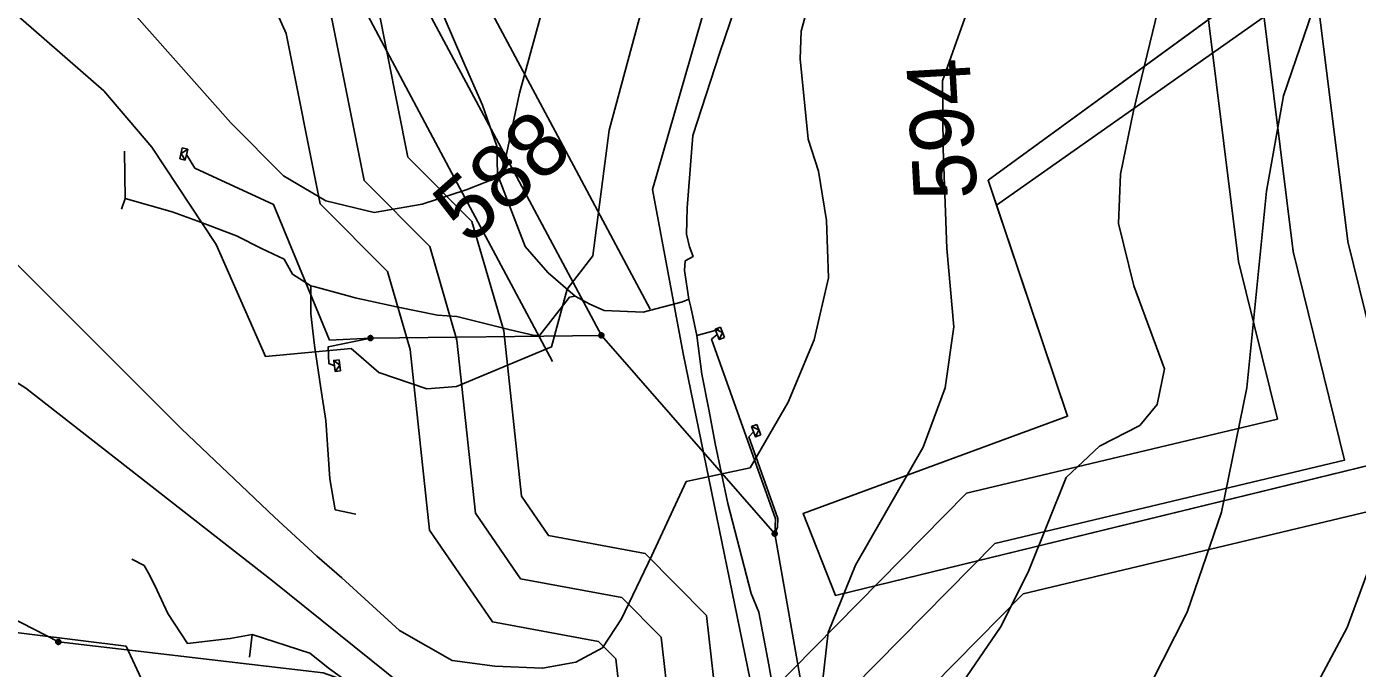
# Model space of a CAD drawing. Extents: x -709418 to -703832, y -1161719 to -1157826.
# Drawn here: x -707200.1 to -707032.1, y -1159896.5 to -1159815.5 of the extents above; entities that cross this region are included whole.
import ezdxf

# ---------------------------------------------------------------- set-up
doc = ezdxf.new("R2010")
doc.units = 0
for name, color, linetype in [('102_obvod PÚ', 7, 'Continuous'), ('110_silnice II. třídy a III. třídy', 7, 'Continuous'), ('120_vrstevnice hlavní', 7, 'Continuous'), ('121_vrstevnice hlavní_popis', 7, 'Continuous'), ('122_vrstevnice základní', 7, 'Continuous'), ('206_TTP_KN', 7, 'Continuous'), ('210_ostatní plocha_KN', 7, 'Continuous'), ('501_vodní tok', 7, 'Continuous'), ('708_el NN nadzemní a podzemní_ E.ON', 7, 'Continuous'), ('717_elektronická komunikace O2', 7, 'Continuous'), ('735_OP sítí TI', 7, 'Continuous')]:
    doc.layers.add(name, color=color, linetype=linetype)

# ---------------------------------------------------------------- blocks, each defined once
blk = doc.blocks.new('Elektro - Implicitní$0$NN4601')
for points in [[(0.63, 0), (0.62, 0.07), (0.61, 0.13), (0.6, 0.2), (0.57, 0.26), (0.54, 0.32), (0.51, 0.37), (0.47, 0.42), (0.42, 0.47), (0.37, 0.51), (0.31, 0.55), (0.25, 0.58), (0.19, 0.6), (0.13, 0.62), (0.06, 0.63), (0, 0.63), (-0.07, 0.63), (-0.13, 0.62), (-0.2, 0.6), (-0.26, 0.58), (-0.32, 0.55), (-0.37, 0.51), (-0.42, 0.47), (-0.47, 0.42), (-0.51, 0.37), (-0.55, 0.32), (-0.58, 0.26), (-0.6, 0.2), (-0.62, 0.13), (-0.63, 0.07), (-0.63, 0), (-0.63, -0.07), (-0.62, -0.13), (-0.6, -0.19), (-0.58, -0.26), (-0.55, -0.31), (-0.51, -0.37), (-0.47, -0.42), (-0.42, -0.47), (-0.37, -0.51), (-0.32, -0.54), (-0.26, -0.57), (-0.2, -0.6), (-0.13, -0.62), (-0.07, -0.63), (0, -0.63), (0.06, -0.63), (0.13, -0.62), (0.19, -0.6), (0.25, -0.57), (0.31, -0.54), (0.37, -0.51), (0.42, -0.47), (0.47, -0.42), (0.51, -0.37), (0.54, -0.31), (0.57, -0.26), (0.6, -0.19), (0.61, -0.13), (0.62, -0.07), (0.63, 0)], [(0.47, 0), (0.47, 0.05), (0.46, 0.1), (0.45, 0.15), (0.43, 0.19), (0.41, 0.24), (0.38, 0.28), (0.35, 0.32), (0.31, 0.35), (0.28, 0.38), (0.23, 0.41), (0.19, 0.43), (0.14, 0.45), (0.1, 0.46), (0.05, 0.47), (0, 0.47), (-0.05, 0.47), (-0.1, 0.46), (-0.15, 0.45), (-0.19, 0.43), (-0.24, 0.41), (-0.28, 0.38), (-0.32, 0.35), (-0.35, 0.32), (-0.38, 0.28), (-0.41, 0.24), (-0.43, 0.19), (-0.45, 0.15), (-0.46, 0.1), (-0.47, 0.05), (-0.47, 0), (-0.47, -0.05), (-0.46, -0.1), (-0.45, -0.15), (-0.43, -0.19), (-0.41, -0.24), (-0.38, -0.28), (-0.35, -0.32), (-0.32, -0.35), (-0.28, -0.38), (-0.24, -0.41), (-0.19, -0.43), (-0.15, -0.45), (-0.1, -0.46), (-0.05, -0.47), (0, -0.47), (0.05, -0.47), (0.1, -0.46), (0.14, -0.45), (0.19, -0.43), (0.23, -0.41), (0.28, -0.38), (0.31, -0.35), (0.35, -0.32), (0.38, -0.28), (0.41, -0.24), (0.43, -0.19), (0.45, -0.15), (0.46, -0.1), (0.47, -0.05), (0.47, 0)], [(0.31, 0), (0.31, 0.03), (0.31, 0.07), (0.3, 0.1), (0.29, 0.13), (0.27, 0.16), (0.25, 0.19), (0.23, 0.21), (0.21, 0.23), (0.18, 0.26), (0.15, 0.27), (0.13, 0.29), (0.09, 0.3), (0.06, 0.31), (0.03, 0.31), (0, 0.32), (-0.04, 0.31), (-0.07, 0.31), (-0.1, 0.3), (-0.13, 0.29), (-0.16, 0.27), (-0.19, 0.26), (-0.21, 0.23), (-0.24, 0.21), (-0.26, 0.19), (-0.28, 0.16), (-0.29, 0.13), (-0.3, 0.1), (-0.31, 0.07), (-0.32, 0.03), (-0.32, 0), (-0.32, -0.03), (-0.31, -0.06), (-0.3, -0.1), (-0.29, -0.13), (-0.28, -0.16), (-0.26, -0.18), (-0.24, -0.21), (-0.21, -0.23), (-0.19, -0.25), (-0.16, -0.27), (-0.13, -0.29), (-0.1, -0.3), (-0.07, -0.31), (-0.04, -0.31), (0, -0.31), (0.03, -0.31), (0.06, -0.31), (0.09, -0.3), (0.13, -0.29), (0.15, -0.27), (0.18, -0.25), (0.21, -0.23), (0.23, -0.21), (0.25, -0.18), (0.27, -0.16), (0.29, -0.13), (0.3, -0.1), (0.31, -0.06), (0.31, -0.03), (0.31, 0)], [(0.15, 0), (0.15, 0.02), (0.15, 0.03), (0.15, 0.05), (0.14, 0.06), (0.13, 0.08), (0.13, 0.09), (0.11, 0.11), (0.1, 0.12), (0.09, 0.13), (0.08, 0.14), (0.06, 0.14), (0.05, 0.15), (0.03, 0.15), (0.01, 0.16), (0, 0.16), (-0.02, 0.16), (-0.04, 0.15), (-0.05, 0.15), (-0.07, 0.14), (-0.08, 0.14), (-0.09, 0.13), (-0.11, 0.12), (-0.12, 0.11), (-0.13, 0.09), (-0.14, 0.08), (-0.15, 0.06), (-0.15, 0.05), (-0.16, 0.03), (-0.16, 0.02), (-0.16, 0), (-0.16, -0.02), (-0.16, -0.03), (-0.15, -0.05), (-0.15, -0.06), (-0.14, -0.08), (-0.13, -0.09), (-0.12, -0.1), (-0.11, -0.12), (-0.09, -0.13), (-0.08, -0.14), (-0.07, -0.14), (-0.05, -0.15), (-0.04, -0.15), (-0.02, -0.16), (0, -0.16), (0.01, -0.16), (0.03, -0.15), (0.05, -0.15), (0.06, -0.14), (0.08, -0.14), (0.09, -0.13), (0.1, -0.12), (0.11, -0.1), (0.13, -0.09), (0.13, -0.08), (0.14, -0.06), (0.15, -0.05), (0.15, -0.03), (0.15, -0.02), (0.15, 0)]]:
    blk.add_lwpolyline(points)
blk = doc.blocks.new('Elektro - Implicitní$0$NN6301')
for points in [[(0, -0.7), (-0.7, 0)], [(-0.7, -0.7), (-0.7, 0), (0.7, 0), (0.7, -0.7)], [(-0.7, -0.7), (0.7, -0.7)], [(0, -0.7), (0.7, 0)]]:
    blk.add_lwpolyline(points)

msp = doc.modelspace()

# ---------------------------------------------------------------- linework, layer by layer
at = {"layer": '102_obvod PÚ'}
msp.add_lwpolyline([(-707010.73, -1159866.04), (-707098, -1159887.31), (-707102.07, -1159876.96), (-707068.67, -1159864.69), (-707078.71, -1159834.91), (-707035.83, -1159803.63), (-707037.98, -1159798.97), (-707026.49, -1159799.82)], dxfattribs=at)
at = {"layer": '110_silnice II. třídy a III. třídy'}
for points in [[(-707796.68, -1159073.19), (-707758.86, -1159190.4), (-707734.44, -1159300.73), (-707726.3, -1159328.96), (-707710.98, -1159361.01), (-707689.44, -1159398.33), (-707672.68, -1159420.33), (-707591.22, -1159519.21), (-707503.14, -1159616.33), (-707475.85, -1159642.64), (-707378.49, -1159735.32), (-707320.09, -1159789.38), (-707255.46, -1159826.22), (-707200.25, -1159861.16), (-707169.1, -1159885.49), (-707119.45, -1159925.38), (-707100.71, -1159937.16)], [(-707024.62, -1159709.14), (-707041.49, -1159737.56), (-707056.44, -1159754.43), (-707079.58, -1159768.89), (-707097.91, -1159784.3), (-707112.85, -1159807.43), (-707121.1, -1159836.07), (-707117.24, -1159856.79), (-707092.17, -1159978.7), (-707074.33, -1160037.97), (-707032.37, -1160169.9), (-707002, -1160241.7)]]:
    msp.add_lwpolyline(points, dxfattribs=at)
at = {"layer": '120_vrstevnice hlavní'}
for points in [[(-707205.15, -1159810.75), (-707190.4, -1159823.62), (-707184.32, -1159830.71), (-707176.22, -1159843.01), (-707169.95, -1159857.17), (-707159.17, -1159856.16), (-707155.66, -1159859.17), (-707149.61, -1159861.23), (-707145.85, -1159860.94), (-707133.84, -1159855.91), (-707131.86, -1159848.66), (-707128.63, -1159844.45), (-707126.57, -1159828.58), (-707121.35, -1159809.21), (-707109.76, -1159787.95)], [(-707019.17, -1159817.65), (-707021.25, -1159822.81), (-707022.72, -1159832.33), (-707024.44, -1159848.71), (-707025.98, -1159863.09), (-707027.8, -1159873.77), (-707029.57, -1159881.11), (-707033.38, -1159891.38)], [(-707216.34, -1159978.04), (-707182.88, -1159987.8), (-707157.42, -1159997.78), (-707138.33, -1160002.69), (-707131.96, -1160002.69), (-707124.44, -1160000.96), (-707117.93, -1159997.78), (-707108.38, -1159989.68), (-707095.54, -1159978.02), (-707089.51, -1159976.77), (-707087.7, -1159971.45), (-707081.19, -1159954.24), (-707068.69, -1159936.85), (-707069.19, -1159933.09), (-707049.95, -1159922.42), (-707033.38, -1159891.38)]]:
    msp.add_lwpolyline(points, dxfattribs=at)
at = {"layer": '122_vrstevnice základní'}
for points in [[(-707052.12, -1159667.7), (-707058.77, -1159683.32), (-707066.58, -1159697.93), (-707075.26, -1159712.25), (-707080.03, -1159722.37), (-707087.55, -1159735.82), (-707094.06, -1159743.64), (-707114.75, -1159772.42), (-707126.03, -1159785.29), (-707131.82, -1159794.69), (-707132.83, -1159797.44), (-707134.56, -1159811.76), (-707137.89, -1159823.91), (-707140.11, -1159834.34), (-707144.62, -1159836.1), (-707150.19, -1159837.94), (-707156.26, -1159838.96), (-707162.34, -1159837.51), (-707167.69, -1159834.33), (-707174.34, -1159827.67), (-707208.48, -1159789.2), (-707227.33, -1159771.32)], [(-707023.48, -1159753.62), (-707035.92, -1159764.32), (-707039.77, -1159767.75), (-707043.66, -1159770.55), (-707049.03, -1159770.81), (-707053.64, -1159776.95), (-707067.94, -1159793.19), (-707074.26, -1159801.48), (-707078.37, -1159808.14), (-707081.64, -1159814.46), (-707084.45, -1159822.37), (-707084.4, -1159830.93), (-707083.9, -1159843.51), (-707083.03, -1159853.41), (-707084.14, -1159861.11), (-707086.92, -1159868.61), (-707095.44, -1159883.48), (-707098.9, -1159891.99), (-707099.86, -1159900.52)], [(-707084.08, -1159901.44), (-707077.14, -1159891.32), (-707073.67, -1159884.37), (-707068.86, -1159872.43), (-707064.62, -1159868.47), (-707059.55, -1159865.85), (-707057.34, -1159863.2), (-707056.44, -1159858.69), (-707060.32, -1159848.25), (-707062.23, -1159840.35), (-707061.97, -1159834.15), (-707060.36, -1159826.13), (-707057.27, -1159813.49), (-707052.94, -1159803.32), (-707046.47, -1159795.54), (-707041.24, -1159792.76), (-707035.99, -1159788.64), (-707027.01, -1159781.03)], [(-707058.19, -1159898.55), (-707053.56, -1159889.44), (-707049.25, -1159876.81), (-707046.03, -1159861.11), (-707043.56, -1159836.26), (-707041.39, -1159824.24), (-707037.73, -1159813.57), (-707031.9, -1159803.6)], [(-707202.26, -1159844.6), (-707180.56, -1159866.29), (-707168.85, -1159877.43), (-707163.48, -1159882.36), (-707160.33, -1159885.09), (-707153.04, -1159891.73), (-707146.38, -1159895.51), (-707141.02, -1159896.26), (-707134.98, -1159896.5), (-707130.78, -1159895.72), (-707127.4, -1159893.92), (-707125, -1159890.26), (-707121.16, -1159882.29), (-707116.84, -1159872.95), (-707108.76, -1159871.22), (-707103.96, -1159862.9), (-707100.66, -1159855.06), (-707098.88, -1159847.2), (-707099.12, -1159839.98), (-707100.14, -1159833.75), (-707101.44, -1159829.7), (-707102.45, -1159819.57), (-707102.31, -1159816.1), (-707100.72, -1159810.17)], [(-707185.12, -1159898.99), (-707187.57, -1159893.71), (-707217.45, -1159890.02), (-707237.26, -1159884.23), (-707261.56, -1159880.04), (-707287.02, -1159874.39), (-707308.43, -1159871.79), (-707324.05, -1159872.66), (-707332.73, -1159874.68), (-707341.41, -1159877.86), (-707351.82, -1159883.51), (-707360.5, -1159886.83), (-707370.91, -1159888.57), (-707388.27, -1159889.87), (-707409.1, -1159893.49), (-707421.25, -1159896.81)]]:
    msp.add_lwpolyline(points, dxfattribs=at)
at = {"layer": '206_TTP_KN'}
for p, q in [((-707077.65, -1159838.04), (-707039.33, -1159811.08)), ((-707068.67, -1159864.69), (-707077.65, -1159838.04)), ((-707102.07, -1159876.96), (-707068.67, -1159864.69)), ((-707017.62, -1159867.72), (-707098, -1159887.31)), ((-707098, -1159887.31), (-707102.07, -1159876.96))]:
    msp.add_line(p, q, dxfattribs=at)
at = {"layer": '210_ostatní plocha_KN'}
for p, q in [((-707078.71, -1159834.91), (-707040.8, -1159807.26)), ((-707039.33, -1159811.08), (-707077.65, -1159838.04)), ((-707077.65, -1159838.04), (-707078.71, -1159834.91))]:
    msp.add_line(p, q, dxfattribs=at)
at = {"layer": '501_vodní tok'}
msp.add_lwpolyline([(-707117.83, -1159911.76), (-707120.01, -1159892.59), (-707124.98, -1159887.57), (-707137.77, -1159885.21), (-707143.44, -1159876.93), (-707145.8, -1159855.09), (-707149.23, -1159843.26), (-707157.52, -1159834.93), (-707161.59, -1159814.53), (-707168, -1159800.19), (-707176.15, -1159790.23), (-707184.16, -1159776.65), (-707186.56, -1159766.68), (-707192.31, -1159754.77), (-707207.48, -1159720.69), (-707222.65, -1159685.23), (-707238.46, -1159647.82)], dxfattribs=at)
at = {"layer": '708_el NN nadzemní a podzemní_ E.ON'}
for points in [[(-707127.55, -1159854.48), (-707139.23, -1159832.61), (-707150.92, -1159810.75), (-707160.51, -1159780.45)], [(-707096.69, -1159911.5), (-707097.56, -1159911.58), (-707098.74, -1159901.93), (-707077.85, -1159880.75), (-707033.69, -1159870.23), (-707040.19, -1159843.89), (-707046.72, -1159791.33), (-707049.68, -1159783.1), (-707056.82, -1159786.08)], [(-707156.71, -1159854.83), (-707161.87, -1159855.08), (-707168.95, -1159837.96), (-707178.89, -1159833.37), (-707179.96, -1159831.67)], [(-707127.55, -1159854.48), (-707156.71, -1159854.83)], [(-707098.68, -1159918.98), (-707105.66, -1159879.52), (-707127.55, -1159854.48)], [(-707105.66, -1159879.52), (-707105.55, -1159877.63), (-707113.63, -1159854.97), (-707112.92, -1159854.36)], [(-707156.71, -1159854.83), (-707162.07, -1159855.94), (-707161.97, -1159858.04), (-707161.27, -1159858.34)], [(-707099.6, -1159919.34), (-707130.61, -1159908.39), (-707162.68, -1159897.07), (-707196.13, -1159893.18), (-707220.82, -1159880.51), (-707245.5, -1159867.84), (-707266.54, -1159866.85), (-707268.56, -1159866.76)], [(-707105.66, -1159879.52), (-707105.31, -1159878.69), (-707105.25, -1159877.59), (-707108.91, -1159867.31), (-707108.33, -1159866.65)]]:
    msp.add_lwpolyline(points, dxfattribs=at)
at = {"layer": '717_elektronická komunikace O2'}
for points in [[(-707155.55, -1159770.95), (-707157, -1159772.76), (-707159.59, -1159775.27), (-707161.97, -1159777.74), (-707163.41, -1159780.99), (-707163.34, -1159783.81), (-707161.81, -1159789.78), (-707159.5, -1159794.87), (-707156.64, -1159798.53), (-707153.56, -1159803.61), (-707152.12, -1159806.76), (-707149.31, -1159811.05), (-707147.4, -1159814.3), (-707145.06, -1159819.8), (-707142.58, -1159825.42), (-707140.75, -1159830.6), (-707140.67, -1159834.16), (-707137.16, -1159843.27), (-707135.49, -1159845.21), (-707134.26, -1159846.59), (-707130.87, -1159849.52)], [(-707116.52, -1159849.9), (-707117.07, -1159846.3), (-707116.97, -1159845.09), (-707115.97, -1159844.54), (-707116.42, -1159843.3), (-707116.82, -1159841.72), (-707116.71, -1159838.38), (-707115.99, -1159829.26), (-707112.62, -1159818.9), (-707108.56, -1159806.88), (-707107.9, -1159805.48), (-707106.35, -1159802.73), (-707101.79, -1159795.1), (-707099.85, -1159792.26), (-707097.89, -1159789.85), (-707096.06, -1159787.35), (-707091.72, -1159782.83), (-707088, -1159779.96)], [(-707097.89, -1159789.85), (-707099.85, -1159792.26), (-707101.79, -1159795.1), (-707106.35, -1159802.73), (-707107.9, -1159805.48), (-707108.56, -1159806.88), (-707112.62, -1159818.9), (-707115.99, -1159829.26), (-707116.71, -1159838.38), (-707116.82, -1159841.72), (-707116.42, -1159843.3), (-707115.97, -1159844.54)], [(-707187.76, -1159831.24), (-707187.69, -1159837.19), (-707188.17, -1159838.56)], [(-707187.69, -1159837.19), (-707187.76, -1159831.24)], [(-707187.69, -1159837.19), (-707188.17, -1159838.56)], [(-707164.24, -1159848.21), (-707166.54, -1159846.75), (-707167.62, -1159844.88), (-707170.48, -1159843.53), (-707173.63, -1159841.91), (-707178.5, -1159840.06), (-707181.75, -1159838.88), (-707187.69, -1159837.19)], [(-707187.69, -1159837.19), (-707181.75, -1159838.88), (-707178.5, -1159840.06), (-707173.63, -1159841.91), (-707170.48, -1159843.53), (-707167.62, -1159844.88), (-707166.54, -1159846.75), (-707164.24, -1159848.21), (-707164.24, -1159851.75), (-707163.78, -1159855.75), (-707163, -1159861.15), (-707162.37, -1159865.23), (-707161.85, -1159872.61), (-707161.19, -1159876.49), (-707158.54, -1159877.04)], [(-707116.52, -1159849.9), (-707117.07, -1159846.3), (-707116.97, -1159845.09), (-707115.97, -1159844.54)], [(-707164.24, -1159848.21), (-707163.87, -1159848.3), (-707159.25, -1159849.58), (-707158.64, -1159849.75)], [(-707164.24, -1159848.21), (-707164.24, -1159851.75), (-707163.78, -1159855.75), (-707163, -1159861.15), (-707162.37, -1159865.23), (-707161.85, -1159872.61), (-707161.19, -1159876.49), (-707158.54, -1159877.04)], [(-707163.87, -1159848.3), (-707159.25, -1159849.58), (-707158.64, -1159849.75), (-707153.43, -1159850.88), (-707148.23, -1159851.92), (-707145.82, -1159852.09), (-707139.07, -1159853.79), (-707135.98, -1159854.48)], [(-707158.64, -1159849.75), (-707153.43, -1159850.88), (-707148.23, -1159851.92), (-707145.82, -1159852.09), (-707139.07, -1159853.79), (-707135.98, -1159854.48), (-707135.34, -1159854.44), (-707131.58, -1159849.67), (-707130.87, -1159849.52)], [(-707131.58, -1159849.67), (-707135.34, -1159854.44)], [(-707130.87, -1159849.52), (-707129.01, -1159850.55), (-707127.2, -1159851.36), (-707122.29, -1159851.54), (-707117.31, -1159850.27), (-707116.52, -1159849.9)], [(-707130.87, -1159849.52), (-707129.01, -1159850.55), (-707127.2, -1159851.36), (-707122.29, -1159851.54)], [(-707122.29, -1159851.54), (-707117.31, -1159850.27), (-707116.52, -1159849.9)], [(-707115.49, -1159854.48), (-707116.25, -1159850.91), (-707116.52, -1159849.9)], [(-707115.49, -1159854.48), (-707112.73, -1159853.73)], [(-707112.73, -1159853.73), (-707115.49, -1159854.48)], [(-707115.49, -1159854.48), (-707114.88, -1159859.36), (-707113.95, -1159864.05), (-707113.18, -1159868.14), (-707111.56, -1159875.69), (-707108.62, -1159887.06), (-707107.67, -1159889.41), (-707106.42, -1159896.09)], [(-707113.95, -1159864.05), (-707114.88, -1159859.36)], [(-707186.85, -1159882.72), (-707185.29, -1159883.53), (-707184.58, -1159884.79), (-707183.67, -1159886.71), (-707182.32, -1159889.61), (-707179.84, -1159893.37), (-707174.43, -1159892.77), (-707171.64, -1159892.23)], [(-707179.84, -1159893.37), (-707182.32, -1159889.61), (-707183.67, -1159886.71)], [(-707108.62, -1159887.06), (-707107.67, -1159889.41), (-707106.42, -1159896.09), (-707104.95, -1159904.3), (-707103.5, -1159911.88), (-707102.11, -1159917.51), (-707101.25, -1159920.63), (-707100.08, -1159922), (-707097.86, -1159923.08), (-707096.31, -1159924.32), (-707094.07, -1159930.23), (-707092.52, -1159937.8), (-707095.25, -1159938.73), (-707095, -1159940.21), (-707094.41, -1159943.29), (-707093.04, -1159950.13)], [(-707179.84, -1159893.37), (-707174.43, -1159892.77), (-707171.64, -1159892.23), (-707171.97, -1159895.1)], [(-707171.64, -1159892.23), (-707171.97, -1159895.1)], [(-707171.64, -1159892.23), (-707164.35, -1159894.62), (-707161.89, -1159896.58), (-707159.21, -1159898.53), (-707159.27, -1159902.28), (-707159.62, -1159906.78), (-707158.64, -1159910.16), (-707158.33, -1159912.43), (-707158.61, -1159917.01), (-707158.38, -1159922.38), (-707157.85, -1159924), (-707156.95, -1159929.5), (-707156.73, -1159930.75)], [(-707171.64, -1159892.23), (-707164.35, -1159894.62), (-707161.89, -1159896.58), (-707159.21, -1159898.53), (-707159.27, -1159902.28), (-707159.62, -1159906.78), (-707158.64, -1159910.16), (-707158.33, -1159912.43), (-707158.61, -1159917.01), (-707158.38, -1159922.38), (-707157.85, -1159924), (-707156.95, -1159929.5), (-707156.73, -1159930.75), (-707156.37, -1159937.68), (-707156.32, -1159941.67), (-707159.41, -1159943.75), (-707163.76, -1159944.81), (-707165.12, -1159943.84)], [(-707106.42, -1159896.09), (-707104.95, -1159904.3), (-707103.5, -1159911.88), (-707102.11, -1159917.51), (-707101.25, -1159920.63), (-707100.08, -1159922), (-707097.86, -1159923.08)]]:
    msp.add_lwpolyline(points, dxfattribs=at)
at = {"layer": '735_OP sítí TI'}
for points in [[(-707111.91, -1159910.73), (-707114.29, -1159889.85), (-707122.03, -1159882.01), (-707134.23, -1159879.76), (-707137.64, -1159874.78), (-707139.89, -1159853.92), (-707143.9, -1159840.12), (-707151.99, -1159831.98), (-707155.84, -1159812.7), (-707162.85, -1159797.01), (-707171.22, -1159786.79), (-707178.54, -1159774.37), (-707180.88, -1159764.65), (-707186.86, -1159752.24), (-707201.99, -1159718.29), (-707217.13, -1159682.89), (-707232.84, -1159645.71)], [(-707123.76, -1159912.78), (-707125.74, -1159895.33), (-707127.92, -1159893.13), (-707141.31, -1159890.65), (-707149.24, -1159879.07), (-707151.7, -1159856.26), (-707154.57, -1159846.41), (-707163.05, -1159837.88), (-707167.34, -1159816.36), (-707173.15, -1159803.37), (-707181.09, -1159793.68), (-707189.78, -1159778.93), (-707192.25, -1159768.71), (-707197.75, -1159757.29), (-707212.98, -1159723.09), (-707228.17, -1159687.58), (-707244.08, -1159649.92)], [(-707091.02, -1159907.4), (-707091.38, -1159904.44), (-707074.28, -1159887.09), (-707025.2, -1159875.4), (-707033.29, -1159842.62), (-707039.87, -1159789.69), (-707045.58, -1159773.81), (-707059.52, -1159779.62)], [(-707121.38, -1159851.18), (-707133.06, -1159829.32), (-707144.44, -1159808.02), (-707153.84, -1159778.34)], [(-707133.72, -1159857.78), (-707145.41, -1159835.91), (-707157.4, -1159813.48), (-707167.18, -1159782.56)], [(-707096.05, -1159918.47), (-707103.68, -1159919.17), (-707106.1, -1159899.42), (-707081.42, -1159874.41), (-707042.18, -1159865.06), (-707047.09, -1159845.16), (-707053.57, -1159792.97), (-707053.78, -1159792.39), (-707054.12, -1159792.54)]]:
    msp.add_lwpolyline(points, dxfattribs=at)

# ---------------------------------------------------------------- block references
at = {"layer": '708_el NN nadzemní a podzemní_ E.ON'}
for p, rotation in [((-707179.96, -1159831.67), -103.5315667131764), ((-707112.92, -1159854.36), 110.9829555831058), ((-707161.27, -1159858.34), 96.53055557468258), ((-707108.33, -1159866.65), 111.02745558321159)]:
    msp.add_blockref('Elektro - Implicitní$0$NN6301', p, dxfattribs=dict(at, rotation=rotation))
for p, xscale, yscale, rotation in [((-707139.24, -1159832.62), 0.5, 0.5, -61.87931658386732), ((-707127.55, -1159854.48), 0.4999999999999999, 0.4999999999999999, -48.840027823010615), ((-707156.71, -1159854.83), 0.5, 0.5, 0.6878388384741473), ((-707105.66, -1159879.52), 0.49999999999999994, 0.5000000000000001, -79.96763052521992), ((-707196.13, -1159893.18), 0.5000000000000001, 0.5, -6.633444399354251)]:
    msp.add_blockref('Elektro - Implicitní$0$NN4601', p, dxfattribs=dict(at, xscale=xscale, yscale=yscale, rotation=rotation))

# ---------------------------------------------------------------- texts
at = {"layer": '121_vrstevnice hlavní_popis'}
for s, rotation, p in [('594', 93.2462, (-707080.07, -1159837.15)), ('588', 41.1276, (-707144.29, -1159843.23))]:
    msp.add_text(s, height=8, rotation=rotation, dxfattribs=at).set_placement(p)

doc.saveas('drawing.dxf')
